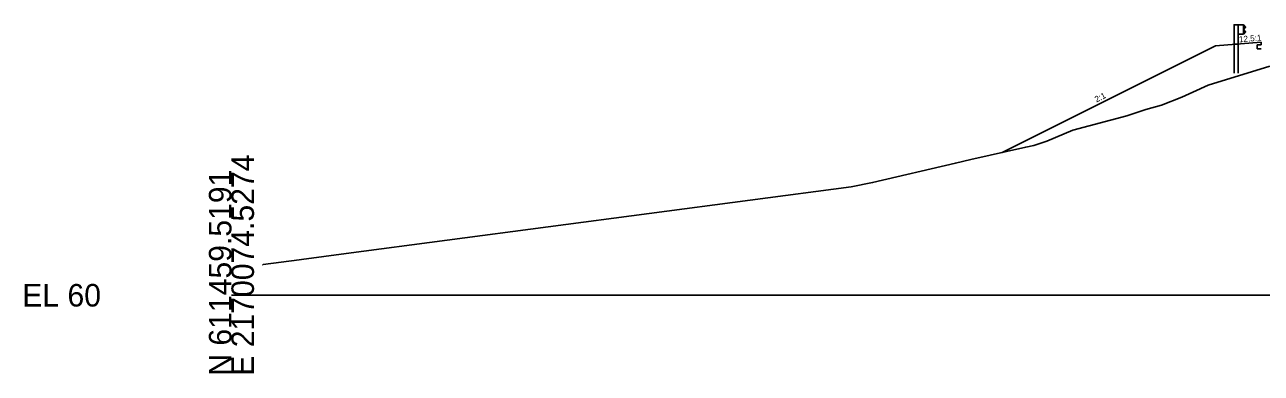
# Model space of a CAD drawing. Extents: x -26 to 1303, y -3010 to 12038.
# Drawn here: x 974.3 to 1128, y 2490.3 to 2533.6 of the extents above; entities that cross this region are included whole.
import ezdxf

# ---------------------------------------------------------------- set-up
doc = ezdxf.new("R2010")
doc.units = 0
for name, color, linetype in [('RD_GPK_XS_Cell', 7, 'Continuous'), ('RD_PD_Final_TrvlWay', 7, 'Continuous'), ('RD_XS_Base', 7, 'Continuous'), ('RD_XS_ExGround', 7, 'Continuous'), ('RD_XS_GR', 7, 'Continuous'), ('RD_XS_Greenside', 7, 'Continuous'), ('RD_XS_Pave', 7, 'Continuous'), ('RD_XS_TieSlope', 7, 'Continuous'), ('RD_XS_TX_ShdSlope', 7, 'Continuous'), ('RD_XS_TX_Slope', 7, 'Continuous')]:
    doc.layers.add(name, color=color, linetype=linetype)

msp = doc.modelspace()

# ---------------------------------------------------------------- linework, layer by layer
at = {"layer": 'RD_GPK_XS_Cell'}
msp.add_line((1000, 2500), (1150, 2500), dxfattribs=at)
at = {"layer": 'RD_PD_Final_TrvlWay'}
for p, q in [((1125.12, 2531.22), (1124.62, 2531.18)), ((1124.62, 2531.18), (1124.62, 2527.61)), ((1125.12, 2527.61), (1125.12, 2531.22))]:
    msp.add_line(p, q, dxfattribs=at)
at = {"layer": 'RD_XS_Base'}
for p, q in [((1128, 2531.13), (1127.5, 2531.11)), ((1127.5, 2531.11), (1127.5, 2531.11)), ((1127.5, 2531.11), (1127.5, 2530.61)), ((1127.5, 2530.61), (1128, 2530.63)), ((1128, 2531.13), (1128, 2531.13)), ((1128, 2530.63), (1128, 2530.63))]:
    msp.add_line(p, q, dxfattribs=at)
at = {"layer": 'RD_XS_ExGround'}
msp.add_lwpolyline([(1003.88, 2503.79), (1003.9, 2503.79), (1003.96, 2503.81), (1008.43, 2504.41), (1008.72, 2504.45), (1014.28, 2505.19), (1077.01, 2513.47), (1079.69, 2514.01), (1089.98, 2516.42), (1091.89, 2516.86), (1098.73, 2518.41), (1099.72, 2518.59), (1101.34, 2519.16), (1104.56, 2520.53), (1111.28, 2522.31), (1113.64, 2523.07), (1115.6, 2523.61), (1118.14, 2524.63), (1119.49, 2525.24), (1121.38, 2526.12), (1129.07, 2528.47)], dxfattribs=at)
at = {"layer": 'RD_XS_GR'}
for points in [[(1125.12, 2533.61), (1125.12, 2531.22), (1124.62, 2531.18), (1124.62, 2533.61), (1124.87, 2533.61), (1125.12, 2533.61)], [(1125.78, 2533.61), (1125.78, 2532.45), (1125.12, 2532.45), (1125.12, 2533.61), (1125.78, 2533.61)], [(1125.78, 2533.61), (1125.78, 2533.61), (1125.78, 2533.61), (1125.78, 2532.45), (1126.05, 2532.74), (1126.05, 2532.74), (1125.78, 2533.03), (1125.78, 2533.03), (1126.05, 2533.32), (1126.05, 2533.32), (1125.78, 2533.61)]]:
    msp.add_lwpolyline(points, dxfattribs=at)
at = {"layer": 'RD_XS_Greenside'}
msp.add_line((1122.3, 2530.99), (1095.81, 2517.75), dxfattribs=at)
at = {"layer": 'RD_XS_Pave'}
for p, q in [((1128, 2531.45), (1128, 2531.45)), ((1128, 2531.45), (1128, 2531.29)), ((1128, 2531.29), (1128, 2531.29)), ((1128, 2531.29), (1128, 2531.13))]:
    msp.add_line(p, q, dxfattribs=at)
at = {"layer": 'RD_XS_TieSlope'}
msp.add_line((1128, 2531.45), (1122.3, 2530.99), dxfattribs=at)

# ---------------------------------------------------------------- texts
at = {"layer": 'RD_GPK_XS_Cell'}
for s, p in [('E 2170074.5274', (1002.8, 2490)), ('N 611459.5191', (1000, 2490))]:
    msp.add_text(s, height=2.8, rotation=90, dxfattribs=at).set_placement(p)
msp.add_text('EL 60', height=2.8, dxfattribs=at).set_placement((974, 2498.6))
at = {"layer": 'RD_XS_TX_ShdSlope'}
msp.add_text('12.5:1', height=0.75, rotation=4.5739, dxfattribs=at).set_placement((1125.26, 2531.42))
at = {"layer": 'RD_XS_TX_Slope'}
msp.add_text('2:1', height=0.75, rotation=26.5651, dxfattribs=at).set_placement((1107.52, 2523.95))

doc.saveas('drawing.dxf')
